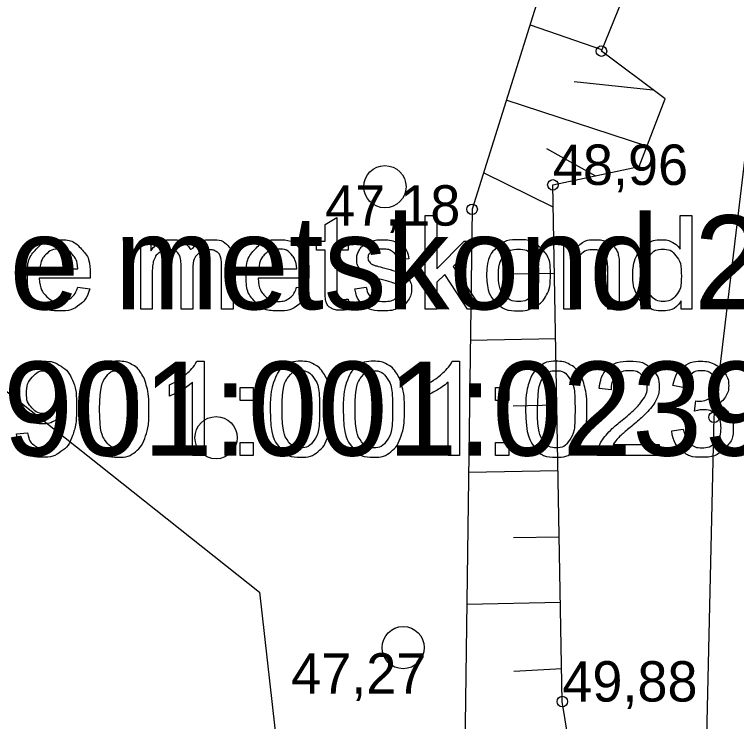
# Model space of a CAD drawing. Extents: x 700746 to 706058, y 6570320 to 6580460.
# Drawn here: x 702789.39 to 702833.18, y 6575736.1 to 6575779 of the extents above; entities that cross this region are included whole.
import ezdxf

# ---------------------------------------------------------------- set-up
doc = ezdxf.new("R2010")
doc.units = 0
for name, color, linetype in [('HALJASTUS', 7, 'Continuous'), ('kataster', 7, 'Continuous'), ('KORGUS-EH2000', 7, 'Continuous'), ('Plokid', 7, 'Continuous'), ('RELJEEF', 7, 'Continuous'), ('TEE', 7, 'Continuous')]:
    doc.layers.add(name, color=color, linetype=linetype)

msp = doc.modelspace()

# ---------------------------------------------------------------- linework, layer by layer
at = {"layer": 'HALJASTUS'}
for centre in [(702811.859, 6575768.555), (702801.62, 6575753.327), (702812.966, 6575740.59)]:
    msp.add_circle(centre, 1.28, dxfattribs=at)
at = {"layer": 'kataster'}
for points in [[(702808.235, 6575762.324), (702808.235, 6575764.704), (702807.718, 6575764.704), (702807.718, 6575765.247), (702808.235, 6575765.247), (702808.235, 6575766.27), (702808.934, 6575766.689), (702808.934, 6575765.247), (702809.634, 6575765.247), (702809.634, 6575764.704), (702808.934, 6575764.704), (702808.934, 6575762.283)], [(702814.307, 6575761.115), (702814.307, 6575766.815), (702815.007, 6575766.815), (702815.007, 6575763.567), (702816.665, 6575765.247), (702817.571, 6575765.247), (702815.993, 6575763.712), (702817.732, 6575761.115), (702816.868, 6575761.115), (702815.495, 6575763.228), (702815.007, 6575762.753), (702815.007, 6575761.115), (702814.307, 6575761.115)], [(702829.77, 6575764.772), (702829.77, 6575766.815), (702830.47, 6575766.815), (702830.47, 6575761.115), (702829.823, 6575761.115)], [(702797.047, 6575761.115), (702797.047, 6575765.247), (702797.672, 6575765.247), (702797.672, 6575764.664)], [(702822.715, 6575761.115), (702822.715, 6575765.247), (702823.345, 6575765.247), (702823.345, 6575764.66)], [(702800.201, 6575763.513), (702800.201, 6575761.115), (702799.502, 6575761.115), (702799.502, 6575763.797)], [(702802.647, 6575763.95), (702802.647, 6575761.115), (702801.947, 6575761.115), (702801.947, 6575763.715)], [(702813.318, 6575764.178), (702812.631, 6575764.087)], [(702790.935, 6575763.574), (702793.242, 6575763.574)], [(702804.207, 6575763.574), (702806.514, 6575763.574)], [(702823.414, 6575763.37), (702823.414, 6575761.115), (702822.715, 6575761.115)], [(702826.069, 6575763.654), (702826.069, 6575761.115), (702825.369, 6575761.115), (702825.369, 6575763.626)], [(702793.977, 6575763.001), (702790.896, 6575763.001)], [(702797.746, 6575763.257), (702797.746, 6575761.115), (702797.047, 6575761.115)], [(702807.249, 6575763.001), (702804.168, 6575763.001)], [(702793.234, 6575762.449), (702793.957, 6575762.358)], [(702806.506, 6575762.449), (702807.23, 6575762.358)], [(702810.038, 6575762.349), (702810.728, 6575762.458)], [(702809.634, 6575761.739), (702809.734, 6575761.121)], [(702829.823, 6575761.115), (702829.823, 6575761.636)], [(702800.445, 6575757.96), (702800.895, 6575757.96), (702800.895, 6575752.238)], [(702815.937, 6575757.96), (702816.388, 6575757.96), (702816.388, 6575752.238)], [(702798.797, 6575755.853), (702798.797, 6575756.529)], [(702800.895, 6575752.238), (702800.196, 6575752.238), (702800.196, 6575756.697)], [(702803.081, 6575755.575), (702803.081, 6575756.37), (702803.876, 6575756.37), (702803.876, 6575755.575), (702803.081, 6575755.575)], [(702814.29, 6575755.853), (702814.29, 6575756.529)], [(702816.388, 6575752.238), (702815.688, 6575752.238), (702815.688, 6575756.697)], [(702818.573, 6575755.575), (702818.573, 6575756.37), (702819.368, 6575756.37), (702819.368, 6575755.575), (702818.573, 6575755.575)], [(702830.021, 6575756.357), (702829.322, 6575756.483)], [(702825.581, 6575756.239), (702824.86, 6575756.313)], [(702830.632, 6575754.94), (702830.709, 6575755.553)], [(702829.252, 6575753.75), (702829.952, 6575753.841)], [(702789.513, 6575753.559), (702790.186, 6575753.62)], [(702803.081, 6575752.238), (702803.081, 6575753.033), (702803.876, 6575753.033), (702803.876, 6575752.238), (702803.081, 6575752.238)], [(702818.573, 6575752.238), (702818.573, 6575753.033), (702819.368, 6575753.033), (702819.368, 6575752.238), (702818.573, 6575752.238)], [(702828.496, 6575752.912), (702828.496, 6575752.238), (702824.729, 6575752.238)], [(702825.702, 6575752.912), (702828.496, 6575752.912)]]:
    msp.add_lwpolyline(points, dxfattribs=at)
for points in [[(702793.957, 6575762.358), (702793.786, 6575761.724), (702793.323, 6575761.374), (702792.861, 6575761.024), (702792.142, 6575761.024), (702791.236, 6575761.024), (702790.705, 6575761.582), (702790.175, 6575762.139), (702790.175, 6575763.146), (702790.175, 6575764.188), (702790.711, 6575764.763), (702791.248, 6575765.338), (702792.103, 6575765.338), (702792.931, 6575765.338), (702793.456, 6575764.774), (702793.98, 6575764.21), (702793.98, 6575763.187), (702793.98, 6575763.125), (702793.977, 6575763.001)], [(702797.672, 6575764.664), (702797.867, 6575764.968), (702798.19, 6575765.153), (702798.513, 6575765.338), (702798.925, 6575765.338), (702799.384, 6575765.338), (702799.678, 6575765.147), (702799.972, 6575764.956), (702800.092, 6575764.613), (702800.583, 6575765.338), (702801.37, 6575765.338), (702801.985, 6575765.338), (702802.316, 6575764.998), (702802.647, 6575764.658), (702802.647, 6575763.95)], [(702807.23, 6575762.358), (702807.058, 6575761.724), (702806.596, 6575761.374), (702806.133, 6575761.024), (702805.414, 6575761.024), (702804.508, 6575761.024), (702803.978, 6575761.582), (702803.447, 6575762.139), (702803.447, 6575763.146), (702803.447, 6575764.188), (702803.984, 6575764.763), (702804.52, 6575765.338), (702805.375, 6575765.338), (702806.203, 6575765.338), (702806.728, 6575764.774), (702807.253, 6575764.21), (702807.253, 6575763.187), (702807.253, 6575763.125), (702807.249, 6575763.001)], [(702810.728, 6575762.458), (702810.787, 6575762.041), (702811.054, 6575761.819), (702811.321, 6575761.597), (702811.801, 6575761.597), (702812.285, 6575761.597), (702812.519, 6575761.794), (702812.753, 6575761.991), (702812.753, 6575762.256), (702812.753, 6575762.493), (702812.546, 6575762.629), (702812.402, 6575762.723), (702811.829, 6575762.867), (702811.059, 6575763.061), (702810.761, 6575763.203), (702810.463, 6575763.345), (702810.309, 6575763.596), (702810.155, 6575763.846), (702810.155, 6575764.149), (702810.155, 6575764.425), (702810.282, 6575764.66), (702810.408, 6575764.895), (702810.626, 6575765.051), (702810.79, 6575765.171), (702811.072, 6575765.255), (702811.355, 6575765.338), (702811.678, 6575765.338), (702812.165, 6575765.338), (702812.533, 6575765.198), (702812.901, 6575765.058), (702813.076, 6575764.818), (702813.252, 6575764.579), (702813.318, 6575764.178)], [(702818.027, 6575763.181), (702818.027, 6575764.328), (702818.665, 6575764.879), (702819.197, 6575765.338), (702819.963, 6575765.338), (702820.814, 6575765.338), (702821.354, 6575764.78), (702821.894, 6575764.223), (702821.894, 6575763.239), (702821.894, 6575762.443), (702821.655, 6575761.986), (702821.416, 6575761.529), (702820.959, 6575761.277), (702820.503, 6575761.024), (702819.963, 6575761.024), (702819.096, 6575761.024), (702818.562, 6575761.58), (702818.027, 6575762.136), (702818.027, 6575763.181)], [(702823.345, 6575764.66), (702823.8, 6575765.338), (702824.658, 6575765.338), (702825.031, 6575765.338), (702825.344, 6575765.204), (702825.657, 6575765.07), (702825.812, 6575764.852), (702825.968, 6575764.634), (702826.03, 6575764.335), (702826.069, 6575764.14), (702826.069, 6575763.654)], [(702829.823, 6575761.636), (702829.43, 6575761.024), (702828.668, 6575761.024), (702828.174, 6575761.024), (702827.759, 6575761.296), (702827.345, 6575761.568), (702827.118, 6575762.056), (702826.89, 6575762.544), (702826.89, 6575763.177), (702826.89, 6575763.795), (702827.096, 6575764.298), (702827.302, 6575764.802), (702827.713, 6575765.07), (702828.125, 6575765.338), (702828.633, 6575765.338), (702829.006, 6575765.338), (702829.297, 6575765.181), (702829.588, 6575765.024), (702829.77, 6575764.772)], [(702793.242, 6575763.574), (702793.195, 6575764.097), (702792.977, 6575764.359), (702792.643, 6575764.765), (702792.11, 6575764.765), (702791.627, 6575764.765), (702791.299, 6575764.441), (702790.97, 6575764.117), (702790.935, 6575763.574)], [(702799.502, 6575763.797), (702799.502, 6575764.263), (702799.33, 6575764.497), (702799.159, 6575764.73), (702798.77, 6575764.73), (702798.474, 6575764.73), (702798.223, 6575764.574), (702797.972, 6575764.419), (702797.859, 6575764.12), (702797.746, 6575763.82), (702797.746, 6575763.257)], [(702801.947, 6575763.715), (702801.947, 6575764.135), (702801.879, 6575764.32), (702801.811, 6575764.504), (702801.632, 6575764.617), (702801.453, 6575764.73), (702801.212, 6575764.73), (702800.777, 6575764.73), (702800.489, 6575764.44), (702800.201, 6575764.151), (702800.201, 6575763.513)], [(702806.514, 6575763.574), (702806.468, 6575764.097), (702806.25, 6575764.359), (702805.915, 6575764.765), (702805.382, 6575764.765), (702804.9, 6575764.765), (702804.571, 6575764.441), (702804.242, 6575764.117), (702804.207, 6575763.574)], [(702812.631, 6575764.087), (702812.585, 6575764.406), (702812.361, 6575764.585), (702812.137, 6575764.765), (702811.728, 6575764.765), (702811.245, 6575764.765), (702811.039, 6575764.605), (702810.833, 6575764.445), (702810.833, 6575764.231), (702810.833, 6575764.095), (702810.918, 6575763.986), (702811.004, 6575763.873), (702811.187, 6575763.799), (702811.292, 6575763.76), (702811.806, 6575763.619), (702812.55, 6575763.421), (702812.844, 6575763.295), (702813.139, 6575763.169), (702813.306, 6575762.928), (702813.474, 6575762.687), (702813.474, 6575762.329), (702813.474, 6575761.98), (702813.27, 6575761.671), (702813.065, 6575761.362), (702812.679, 6575761.193), (702812.294, 6575761.024), (702811.807, 6575761.024), (702811, 6575761.024), (702810.577, 6575761.358), (702810.155, 6575761.692), (702810.038, 6575762.349)], [(702818.748, 6575763.181), (702818.748, 6575762.387), (702819.094, 6575761.992), (702819.439, 6575761.597), (702819.963, 6575761.597), (702820.482, 6575761.597), (702820.827, 6575761.994), (702821.173, 6575762.391), (702821.173, 6575763.204), (702821.173, 6575763.971), (702820.826, 6575764.365), (702820.478, 6575764.76), (702819.963, 6575764.76), (702819.439, 6575764.76), (702819.094, 6575764.367), (702818.748, 6575763.974), (702818.748, 6575763.181)], [(702825.369, 6575763.626), (702825.369, 6575764.054), (702825.288, 6575764.265), (702825.206, 6575764.477), (702824.998, 6575764.604), (702824.79, 6575764.73), (702824.51, 6575764.73), (702824.064, 6575764.73), (702823.739, 6575764.446), (702823.414, 6575764.162), (702823.414, 6575763.37)], [(702827.611, 6575763.177), (702827.611, 6575762.383), (702827.946, 6575761.99), (702828.28, 6575761.597), (702828.735, 6575761.597), (702829.194, 6575761.597), (702829.515, 6575761.973), (702829.836, 6575762.348), (702829.836, 6575763.119), (702829.836, 6575763.967), (702829.509, 6575764.363), (702829.182, 6575764.76), (702828.704, 6575764.76), (702828.237, 6575764.76), (702827.924, 6575764.379), (702827.611, 6575763.998), (702827.611, 6575763.177)], [(702790.896, 6575763.001), (702790.935, 6575762.32), (702791.281, 6575761.959), (702791.627, 6575761.597), (702792.145, 6575761.597), (702792.53, 6575761.597), (702792.802, 6575761.801), (702793.074, 6575762.004), (702793.234, 6575762.449)], [(702804.168, 6575763.001), (702804.207, 6575762.32), (702804.553, 6575761.959), (702804.9, 6575761.597), (702805.417, 6575761.597), (702805.802, 6575761.597), (702806.075, 6575761.801), (702806.347, 6575762.004), (702806.506, 6575762.449)], [(702809.734, 6575761.121), (702809.438, 6575761.059), (702809.206, 6575761.059), (702808.825, 6575761.059), (702808.615, 6575761.179), (702808.406, 6575761.3), (702808.32, 6575761.497), (702808.235, 6575761.694), (702808.235, 6575762.324)], [(702808.934, 6575762.283), (702808.934, 6575761.983), (702808.971, 6575761.898), (702809.008, 6575761.812), (702809.091, 6575761.761), (702809.174, 6575761.71), (702809.328, 6575761.71), (702809.444, 6575761.71), (702809.634, 6575761.739)], [(702790.186, 6575753.62), (702790.272, 6575753.145), (702790.512, 6575752.93), (702790.753, 6575752.716), (702791.13, 6575752.716), (702791.452, 6575752.716), (702791.696, 6575752.864), (702791.94, 6575753.012), (702792.094, 6575753.259), (702792.248, 6575753.506), (702792.353, 6575753.926), (702792.458, 6575754.346), (702792.458, 6575754.782), (702792.458, 6575754.829), (702792.454, 6575754.922), (702792.244, 6575754.587), (702791.881, 6575754.379), (702791.518, 6575754.171), (702791.094, 6575754.171), (702790.387, 6575754.171), (702789.898, 6575754.684), (702789.409, 6575755.197), (702789.409, 6575756.037), (702789.409, 6575756.903), (702789.919, 6575757.431), (702790.43, 6575757.96), (702791.199, 6575757.96), (702791.755, 6575757.96), (702792.215, 6575757.661), (702792.676, 6575757.361), (702792.915, 6575756.808), (702793.153, 6575756.254), (702793.153, 6575755.205), (702793.153, 6575754.113), (702792.916, 6575753.466), (702792.679, 6575752.819), (702792.211, 6575752.481), (702791.743, 6575752.143), (702791.114, 6575752.143), (702790.445, 6575752.143), (702790.022, 6575752.514), (702789.598, 6575752.886), (702789.513, 6575753.559)], [(702793.836, 6575755.049), (702793.836, 6575756.06), (702794.043, 6575756.677), (702794.251, 6575757.294), (702794.661, 6575757.627), (702795.071, 6575757.96), (702795.693, 6575757.96), (702796.151, 6575757.96), (702796.498, 6575757.775), (702796.845, 6575757.591), (702797.069, 6575757.243), (702797.294, 6575756.895), (702797.422, 6575756.396), (702797.55, 6575755.896), (702797.55, 6575755.049), (702797.55, 6575754.047), (702797.344, 6575753.43), (702797.138, 6575752.813), (702796.728, 6575752.478), (702796.318, 6575752.143), (702795.693, 6575752.143), (702794.869, 6575752.143), (702794.399, 6575752.731), (702793.836, 6575753.444), (702793.836, 6575755.049)], [(702798.797, 6575756.529), (702799.384, 6575756.805), (702799.823, 6575757.198), (702800.262, 6575757.591), (702800.445, 6575757.96)], [(702804.901, 6575755.049), (702804.901, 6575756.06), (702805.109, 6575756.677), (702805.317, 6575757.294), (702805.727, 6575757.627), (702806.137, 6575757.96), (702806.758, 6575757.96), (702807.217, 6575757.96), (702807.564, 6575757.775), (702807.911, 6575757.591), (702808.135, 6575757.243), (702808.359, 6575756.895), (702808.487, 6575756.396), (702808.616, 6575755.896), (702808.616, 6575755.049), (702808.616, 6575754.047), (702808.41, 6575753.43), (702808.204, 6575752.813), (702807.794, 6575752.478), (702807.384, 6575752.143), (702806.758, 6575752.143), (702805.935, 6575752.143), (702805.464, 6575752.731), (702804.901, 6575753.444), (702804.901, 6575755.049)], [(702809.328, 6575755.049), (702809.328, 6575756.06), (702809.536, 6575756.677), (702809.744, 6575757.294), (702810.154, 6575757.627), (702810.564, 6575757.96), (702811.185, 6575757.96), (702811.644, 6575757.96), (702811.991, 6575757.775), (702812.338, 6575757.591), (702812.562, 6575757.243), (702812.786, 6575756.895), (702812.914, 6575756.396), (702813.043, 6575755.896), (702813.043, 6575755.049), (702813.043, 6575754.047), (702812.837, 6575753.43), (702812.631, 6575752.813), (702812.221, 6575752.478), (702811.811, 6575752.143), (702811.185, 6575752.143), (702810.362, 6575752.143), (702809.892, 6575752.731), (702809.328, 6575753.444), (702809.328, 6575755.049)], [(702814.29, 6575756.529), (702814.876, 6575756.805), (702815.315, 6575757.198), (702815.755, 6575757.591), (702815.937, 6575757.96)], [(702820.394, 6575755.049), (702820.394, 6575756.06), (702820.601, 6575756.677), (702820.809, 6575757.294), (702821.219, 6575757.627), (702821.629, 6575757.96), (702822.251, 6575757.96), (702822.709, 6575757.96), (702823.056, 6575757.775), (702823.403, 6575757.591), (702823.627, 6575757.243), (702823.852, 6575756.895), (702823.98, 6575756.396), (702824.108, 6575755.896), (702824.108, 6575755.049), (702824.108, 6575754.047), (702823.902, 6575753.43), (702823.696, 6575752.813), (702823.286, 6575752.478), (702822.876, 6575752.143), (702822.251, 6575752.143), (702821.427, 6575752.143), (702820.957, 6575752.731), (702820.394, 6575753.444), (702820.394, 6575755.049)], [(702824.86, 6575756.313), (702824.934, 6575757.117), (702825.416, 6575757.539), (702825.898, 6575757.96), (702826.711, 6575757.96), (702827.531, 6575757.96), (702828.009, 6575757.505), (702828.487, 6575757.051), (702828.487, 6575756.378), (702828.487, 6575756.036), (702828.348, 6575755.706), (702828.208, 6575755.376), (702827.884, 6575755.011), (702827.559, 6575754.645), (702826.806, 6575754.008), (702826.177, 6575753.479), (702825.998, 6575753.291), (702825.819, 6575753.102), (702825.702, 6575752.912)], [(702829.322, 6575756.483), (702829.45, 6575757.186), (702829.905, 6575757.573), (702830.36, 6575757.96), (702831.037, 6575757.96), (702831.504, 6575757.96), (702831.897, 6575757.76), (702832.29, 6575757.56), (702832.498, 6575757.215), (702832.706, 6575756.869), (702832.706, 6575756.481), (702832.706, 6575756.112), (702832.508, 6575755.809), (702832.309, 6575755.507), (702831.92, 6575755.328), (702832.426, 6575755.212), (702832.705, 6575754.844), (702832.984, 6575754.477), (702832.984, 6575753.926), (702832.984, 6575753.18), (702832.44, 6575752.661), (702831.895, 6575752.143), (702831.064, 6575752.143), (702830.313, 6575752.143), (702829.818, 6575752.59), (702829.322, 6575753.038), (702829.252, 6575753.75)], [(702792.376, 6575756.072), (702792.376, 6575756.674), (702792.057, 6575757.028), (702791.738, 6575757.382), (702791.286, 6575757.382), (702790.818, 6575757.382), (702790.474, 6575757.001), (702790.13, 6575756.62), (702790.13, 6575756.013), (702790.13, 6575755.469), (702790.456, 6575755.129), (702790.783, 6575754.788), (702791.266, 6575754.788), (702791.751, 6575754.788), (702792.064, 6575755.129), (702792.376, 6575755.469), (702792.376, 6575756.072)], [(702794.557, 6575755.049), (702794.557, 6575753.643), (702794.884, 6575753.18), (702795.212, 6575752.716), (702795.693, 6575752.716), (702796.174, 6575752.716), (702796.501, 6575753.182), (702796.829, 6575753.647), (702796.829, 6575755.049), (702796.829, 6575756.457), (702796.502, 6575756.919), (702796.175, 6575757.382), (702795.685, 6575757.382), (702795.204, 6575757.382), (702794.916, 6575756.974), (702794.557, 6575756.453), (702794.557, 6575755.049)], [(702805.622, 6575755.049), (702805.622, 6575753.643), (702805.95, 6575753.18), (702806.278, 6575752.716), (702806.758, 6575752.716), (702807.239, 6575752.716), (702807.567, 6575753.182), (702807.894, 6575753.647), (702807.894, 6575755.049), (702807.894, 6575756.457), (702807.567, 6575756.919), (702807.24, 6575757.382), (702806.751, 6575757.382), (702806.27, 6575757.382), (702805.982, 6575756.974), (702805.622, 6575756.453), (702805.622, 6575755.049)], [(702810.049, 6575755.049), (702810.049, 6575753.643), (702810.377, 6575753.18), (702810.705, 6575752.716), (702811.185, 6575752.716), (702811.666, 6575752.716), (702811.994, 6575753.182), (702812.321, 6575753.647), (702812.321, 6575755.049), (702812.321, 6575756.457), (702811.994, 6575756.919), (702811.667, 6575757.382), (702811.178, 6575757.382), (702810.697, 6575757.382), (702810.409, 6575756.974), (702810.049, 6575756.453), (702810.049, 6575755.049)], [(702821.115, 6575755.049), (702821.115, 6575753.643), (702821.442, 6575753.18), (702821.77, 6575752.716), (702822.251, 6575752.716), (702822.732, 6575752.716), (702823.059, 6575753.182), (702823.387, 6575753.647), (702823.387, 6575755.049), (702823.387, 6575756.457), (702823.06, 6575756.919), (702822.733, 6575757.382), (702822.243, 6575757.382), (702821.762, 6575757.382), (702821.474, 6575756.974), (702821.115, 6575756.453), (702821.115, 6575755.049)], [(702824.729, 6575752.238), (702824.722, 6575752.491), (702824.811, 6575752.725), (702824.955, 6575753.11), (702825.272, 6575753.483), (702825.59, 6575753.856), (702826.187, 6575754.345), (702827.115, 6575755.108), (702827.441, 6575755.553), (702827.766, 6575755.998), (702827.766, 6575756.395), (702827.766, 6575756.811), (702827.469, 6575757.096), (702827.172, 6575757.382), (702826.695, 6575757.382), (702826.19, 6575757.382), (702825.888, 6575757.079), (702825.585, 6575756.776), (702825.581, 6575756.239)], [(702830.709, 6575755.553), (702830.779, 6575755.545), (702830.822, 6575755.545), (702831.269, 6575755.545), (702831.627, 6575755.778), (702831.985, 6575756.011), (702831.985, 6575756.497), (702831.985, 6575756.881), (702831.724, 6575757.134), (702831.464, 6575757.386), (702831.051, 6575757.386), (702830.643, 6575757.386), (702830.371, 6575757.129), (702830.099, 6575756.872), (702830.021, 6575756.357)], [(702800.196, 6575756.697), (702799.943, 6575756.456), (702799.533, 6575756.215), (702799.123, 6575755.974), (702798.797, 6575755.853)], [(702815.688, 6575756.697), (702815.436, 6575756.456), (702815.026, 6575756.215), (702814.616, 6575755.974), (702814.29, 6575755.853)], [(702829.952, 6575753.841), (702830.072, 6575753.246), (702830.361, 6575752.983), (702830.649, 6575752.72), (702831.067, 6575752.72), (702831.563, 6575752.72), (702831.902, 6575753.063), (702832.241, 6575753.405), (702832.241, 6575753.91), (702832.241, 6575754.392), (702831.926, 6575754.705), (702831.611, 6575755.018), (702831.125, 6575755.018), (702830.927, 6575755.018), (702830.632, 6575754.94)]]:
    msp.add_open_spline(points, degree=3, dxfattribs=at)
at = {"layer": 'KORGUS-EH2000'}
for centre in [(702824.988, 6575776.779), (702822.045, 6575768.662), (702817.145, 6575767.184), (702831.817, 6575754.565), (702822.618, 6575737.317)]:
    msp.add_circle(centre, 0.32, dxfattribs=at)
at = {"layer": 'Plokid'}
msp.add_lwpolyline([(702742.56, 6575764.72), (702772.31, 6575769.32), (702804.25, 6575743.96), (702819.45, 6575609.09), (702719.35, 6575586.09), (702694.82, 6575611.73)], close=True, dxfattribs=at)
at = {"layer": 'RELJEEF'}
for p, q in [((702825.023, 6575776.864), (702820.697, 6575778.354)), ((702823.327, 6575774.946), (702828.116, 6575774.435)), ((702827.74, 6575771.009), (702819.203, 6575773.81)), ((702821.653, 6575770.88), (702824.637, 6575769.222)), ((702822.069, 6575767.315), (702817.838, 6575769.395)), ((702819.617, 6575763.269), (702822.142, 6575763.316)), ((702822.216, 6575759.316), (702817.036, 6575759.222)), ((702819.635, 6575755.268), (702822.289, 6575755.317)), ((702822.362, 6575751.318), (702816.927, 6575751.218)), ((702819.654, 6575747.267), (702822.435, 6575747.318)), ((702822.509, 6575743.319), (702816.818, 6575743.215)), ((702819.671, 6575739.162), (702822.582, 6575739.32))]:
    msp.add_line(p, q, dxfattribs=at)
for points in [[(702828.374, 6575684.718), (702829.258, 6575696.658), (702822.618, 6575737.317), (702822.045, 6575768.662), (702827.269, 6575769.789), (702828.85, 6575773.886), (702824.988, 6575776.779), (702832.06, 6575794.199), (702834.228, 6575822.584), (702827.084, 6575831.58), (702838.4, 6575843.222), (702838.725, 6575866.03), (702838.725, 6575891.117), (702841.89, 6575945.315), (702837.229, 6575970.209), (702822.356, 6575995.387), (702798.58, 6576020.939)], [(702797.404, 6576019.449), (702821.324, 6575993.006), (702834.006, 6575967.923), (702837.82, 6575941.623), (702833.511, 6575894.054), (702831.172, 6575843.473), (702822.002, 6575831.783), (702828.312, 6575819.529), (702824.938, 6575792.021), (702817.145, 6575767.184), (702816.699, 6575734.454), (702825.742, 6575693.019), (702823.333, 6575626.618), (702826.963, 6575601.89), (702832.233, 6575570.085), (702842.59, 6575518.19), (702856.267, 6575484.057), (702868.074, 6575485.716)]]:
    msp.add_lwpolyline(points, dxfattribs=at)
at = {"layer": 'TEE'}
msp.add_lwpolyline([(702830.027, 6575684.968), (702831.152, 6575725.51), (702831.817, 6575754.565), (702835.347, 6575784.08), (702835.644, 6575813.072), (702839.086, 6575843.28), (702841.092, 6575866.647), (702842.664, 6575897.87), (702846.655, 6575935.935), (702841.574, 6575967.648), (702838.099, 6575974.634), (702830.651, 6575991.099), (702817.57, 6576005.083), (702798.577, 6576023.982), (702784.187, 6576040.099), (702774.299, 6576061.057), (702771.808, 6576073.949), (702774.342, 6576099.093)], dxfattribs=at)

# ---------------------------------------------------------------- texts
at = {"layer": 'kataster'}
for s, p in [('Ahtme metskond 25', (702771.298, 6575761.115)), ('22901:001:0239', (702780.224, 6575752.238))]:
    msp.add_text(s, height=5.7, dxfattribs=at).set_placement(p)
at = {"layer": 'KORGUS-EH2000'}
for s, p in [('48,96 ', (702822.045, 6575768.662)), ('47,18 ', (702808.233, 6575766.193)), ('47,27 ', (702806.172, 6575737.801)), ('49,88 ', (702822.618, 6575737.317))]:
    msp.add_text(s, height=2.45, dxfattribs=at).set_placement(p)

doc.saveas('drawing.dxf')
